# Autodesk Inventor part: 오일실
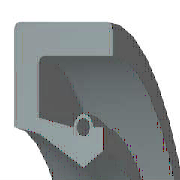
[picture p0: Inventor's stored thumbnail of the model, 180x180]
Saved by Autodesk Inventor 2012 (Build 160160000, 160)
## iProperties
IsCustomPart: 1
Company: 한국ATC센터
Created: 2014-11
Part Number: 오일실
Material: 고무
Description: 오일-실
Document SubType Name: Modeling
Standard: KS B 2804
Designer: KYOUNG IL JANG
Standards Organization: KS
Language: ko-KR
Size Designation: S - 25 40 8
Categories: <MemberInstance><Categories><Category DisplayName="샤프트 부품" InternalName="7f7aeb1f-a693-4053-b835-cee3144e0d98" Mnemonic="SHFT"><Category DisplayName="실링" Intern
Density: 0.93 g/cm^3
Mass: 2.48215 g
Surface Area: 40.3381 cm^2
Volume: 2.66898 cm^3
Author: KYOUNG IL JANG
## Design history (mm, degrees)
revolve "본체" stored, may be unused: angle "d17" = 90 deg
revolve "스프링1" stored, may be unused: angle "d18" = 90 deg
body "Solid1"
sketch "스케치1"
  geometry: L1 (0, 20)-(8, 20); L2 (8, 20)-(8, 18.75); L3 (8, 18.75)-(1.75, 18.75); L4 (0, 20)-(0, 14.6); L5 (0, 14.6)-(1.75, 14.25); L6 (1.75, 14.25)-(4.9, 12.5); L7 (4.9, 12.5)-(0, 12.5); L8 (6.3, 13.375)-(6.3, 14.6); L9 (0, 0)-(9.586, 0) reference; L10 (4.9, 12.5)-(6.3, 13.375); L11 (0, 18)-(0, -3) reference; L12 (-1.917, 0)-(11.503, 0) reference; L13 (4.2, 14.6)-(1.75, 15.09); L14 (1.75, 15.09)-(1.75, 18.75); L15 (6.3, 14.6)-(5.6, 14.6); C1 r 0.455 at (4.9, 14.6); A1 r 0.7 centre (4.9, 14.6) between (5.6, 14.6) and (4.2, 14.6)
  constraints: 26 end point, 5 horizontal alignment, 4 perpendicular, 2 centre point, 2 collinear, 2 horizontal, 2 parallel, 2 point on circle, 2 point on line, 2 vertical alignment, 1 coincident
  dimensions: "d0" = 40 diameter of L1 L9 (= SD2); "d1" = 26.75 diameter of L8.start L9 (= ABDM); "d2" = 1.25 distance of L1.end L2.end (computed from SD); "d3" = 0.91 diameter of C1 (= SPDI); "d4" = 1.4 diameter of A1 (= SPDA); "d5" = 25 diameter of L6.end L9 (= NND); "d6" = 28.5 diameter of L5.end L9 (= TKDM); "d7" = 29.2 diameter of L4.end L9 (= HLDM); "d8" = 4.9 distance from line of C1.centre L4 (= SPDST); "d9" = 6.3 distance between parallel lines of L8 L4 (= SDI); "d10" = 8 distance between parallel lines of L2 L4 (= SWDT); "d12" = 1.75 distance between parallel lines of L14 L4 (= SD)
fillet "모깎기1" dims "d11" = 0.3 (= RR)
other parameters: "SD2" = 40 [user parameter; used in 1 equation term], "SWDT" = 8 [user parameter; used in 1 equation term], "RR" = 0.3 [user parameter; used in 1 equation term], "SD" = 1.75 [user parameter; used in 2 equation terms], "NND" = 25 [user parameter; used in 1 equation term], "SPDA" = 1.4 [user parameter; used in 1 equation term], "SPDI" = 0.91 [user parameter; used in 1 equation term], "TKDM" = 28.5 [user parameter; used in 1 equation term], "HLDM" = 29.2 [user parameter; used in 1 equation term], "ABDM" = 26.75 [user parameter; used in 1 equation term], "SDI" = 6.3 [user parameter; used in 1 equation term], "SPDST" = 4.9 [user parameter; used in 1 equation term], "d13" = 0, "d14" = 0, "d15" = 0, "LAB" = 0.35 [user parameter]
